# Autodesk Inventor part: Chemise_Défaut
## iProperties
Shininess: 64.0
Length Units: 11269
Angle Units: 11279
Time Units: 11290
Mass Units: 11283
Length Display Precision: 3
Angle Display Precision: 2
Compacted: True
Part Number: Chemise_Défaut
Document SubType Name: Modeling
Created: 2006-01
Material: Par défaut
Designer: riri
Density: 0.0
Volumn: 0.0
Area: 0.0
PropertySet Name: Model Information
Control State: 0
Master: False
Checked Out: False
Author: riri
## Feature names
1. Base1
